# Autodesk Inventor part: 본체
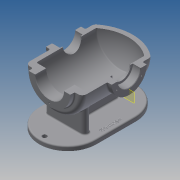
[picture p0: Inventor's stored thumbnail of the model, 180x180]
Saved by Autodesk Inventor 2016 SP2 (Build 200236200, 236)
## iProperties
Created: 2016-02
Part Number: 본체
Material: 알루미늄 6061
Document SubType Name: Modeling
Designer: mduedu
Density: 2.71 g/cm^3
Mass: 2160.77 g
Surface Area: 1521.8 cm^2
Volume: 797.331 cm^3
Appearance: 기본값
Author: mduedu
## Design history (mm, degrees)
sketch "스케치2"
  geometry: L1 (0, 90)-(0, -90); L2 (65, -65.993)-(65, 90); L3 (65, 90)-(0, 90); A1 r 100 centre (0, 10) between (0, -90) and (65, -65.993); 2 further points
  constraints: 6 end point, 2 point on circle, 1 centre point, 1 coincident, 1 horizontal, 1 midpoint, 1 parallel, 1 point on line, 1 vertical
  dimensions: "d3" = 180 distance of L1.start L1.end; "d5" = 130 diameter of L2 L1; "d6" = 100 radius of A1
revolve "회전1" sketch "스케치2" stored, may be unused: angle "d7" = 90 deg
sketch "스케치3"
  geometry: C1 r 47.5 at (0, 0); 1 further point
  constraints: 1 centre point, 1 coincident
  dimensions: "d8" = 95 diameter of C1
extrude "돌출2" join sketch "스케치3" distance "d10" = 10; taper "d11" = 0 deg
sketch "스케치5"
  geometry: L1 (47.5, 100)-(47.5, 90) reference; L2 (47.5, 90)-(65, 90) reference; L3 (65, 90)-(65, -65.993) reference; L4 (-65, -65.993)-(-65, 90) reference; L5 (-65, 90)-(-47.5, 90) reference; L6 (-47.5, 90)-(-47.5, 100) reference; L7 (-47.5, 100)-(47.5, 100) reference; L8 (55, 75)-(55, -61.239); L9 (0, 75)-(55, 75); L10 (0, 75)-(0, -80); A1 r 100 centre (0, 10) between (-65, -65.993) and (0, -90) reference; A2 r 100 centre (0, 10) between (0, -90) and (65, -65.993) reference; A3 r 90 centre (0, 10) between (0, -80) and (55, -61.239); 1 further point
  constraints: 6 end point, 2 point on circle, 1 centre point, 1 parallel, 1 perpendicular, 1 point on line, 1 vertical
  dimensions: "d13" = 10 distance between parallel lines of L3 L8; "d14" = 10 radial gap between concentric circles of A3 A1; "d15" = 15 distance between parallel lines of L9 L2
revolve "회전2" sketch "스케치5" stored, may be unused: angle "d16" = 90 deg
hole "구멍1" diameter "d19" = 65; stored, may be unused: countersink angle "d23" = 90 deg, drill point angle "d25" = 118 deg; dims "d17" = 10, "d18" = 10, "d20" = 6, "d21" = 4, "d22" = 2, "d24" = 8
node "작업 평면1"
sketch "스케치6"
  geometry: L1 (47.5, 100)-(-47.5, 100) reference; C1 r 40 at (0, -7); 1 further point
  constraints: 1 centre point, 1 vertical alignment
  dimensions: "d27" = 80 diameter of C1; "d29" = 107 distance from line of C1.centre L1
extrude "돌출3" join sketch "스케치6" stored distance "d30" = 10; taper "d31" = 0 deg
hole "구멍2" diameter "d34" = 42; stored, may be unused: countersink angle "d38" = 90 deg, drill point angle "d40" = 118 deg; dims "d32" = 10, "d33" = 10, "d35" = 6, "d36" = 52, "d37" = 18, "d39" = 8
sketch "스케치7" dims "d41" = 65
  geometry: C1 r 40 at (0, 0) reference; 3 further points
  constraints: 2 vertical alignment, 1 coincident, 2 other
hole "구멍3" sketch "스케치7" at (0, 32.5) diameter "d43" = 3.242; stored, may be unused: countersink angle "d47" = 90 deg, drill point angle "d49" = 118 deg; dims "d44" = 11, "d45" = 13, "d46" = 18, "d48" = 13
sketch "스케치8" dims "d53" = 80
  geometry: 3 further points
  constraints: 2 vertical alignment, 1 coincident, 2 other
hole "구멍4" sketch "스케치8" at (0, -40) diameter "d56" = 3.242; stored, may be unused: countersink angle "d60" = 90 deg, drill point angle "d62" = 118 deg; dims "d57" = 11, "d58" = 13, "d59" = 18, "d61" = 13
fillet "모깎기1" dims "d66" = 10
fillet "모깎기2" dims "d67" = 3
fillet "모깎기3" dims "d68" = 1
chamfer "모따기1" distance "d69" = 1; stored, may be unused: second distance "d70" = 2, angle "d71" = 45 deg
node "작업 평면5"
sketch "스케치10"
  geometry: L1 (-45, 66)-(45, 66); L2 (45, 66)-(45, 50); L3 (45, 50)-(-45, 50); L4 (-45, 50)-(-45, 66); 2 further points
  constraints: 8 end point, 2 horizontal, 2 vertical, 1 midpoint, 1 vertical alignment
  dimensions: "d177" = 50 distance from line of L3 point (0, 0); "d178" = 90 distance of L1.start L1.end; "d179" = 16 distance of L3.end L1.start
extrude "돌출5" join sketch "스케치10" stored distance "d84" = 10; taper "d85" = 0 deg
sketch "스케치21" dims "d180" = 220, "d182" = 130
  geometry: L1 (65, 58)-(-65, 58); L2 (-65, 58)-(-65, -32); L3 (-65, -32)-(65, -32); L4 (65, -32)-(65, 58); L5 (45, 50)-(45, 66) reference; 4 further points
  constraints: 8 end point, 3 horizontal alignment, 3 midpoint, 2 parallel, 1 horizontal, 1 perpendicular, 1 vertical alignment, 4 other
extrude "돌출13" join sketch "스케치21" distance "d183" = 10; taper "d184" = 0 deg
sketch "스케치11"
  geometry: L1 (-65, 80)-(-65, -61.239) reference; L2 (-100, -97)-(-100, -32) reference; L3 (-65, -45.829)-(-100, -52); L4 (-100, -97)-(-110, -97) reference; 1 further point
  constraints: 2 end point, 2 point on line
  dimensions: "d185" = 45 distance from line of L3.end L4; "d186" = 100 deg angle of L2 L3
feature "리브1" sketch "스케치11" dims "d88" = 1, "d89" = 16, "d90" = 0, "d91" = 0, "d92" = 1, "d93" = 1
fillet "모깎기12"
fillet "모깎기13"
fillet "모깎기16" dims "d167" = 3
fillet "모깎기18"
fillet "모깎기17" dims "d168" = 3
fillet "모깎기19" dims "d187" = 3
node "작업 평면6"
sketch "스케치19"
  geometry: L1 (75, -47)-(75, 33) reference; L2 (-75, -47)-(-75, 33) reference; L3 (75, -7)-(-75, -7); C1 r 22.5 at (0, -7); 1 further point
  constraints: 3 midpoint, 2 end point, 1 centre point
  dimensions: "d149" = 45 diameter of C1
extrude "돌출11" join sketch "스케치19" stored distance "d150" = 10; taper "d151" = 0 deg
hole "구멍6" diameter "d154" = 33.376; stored, may be unused: countersink angle "d158" = 90 deg, drill point angle "d160" = 118 deg; dims "d155" = 6, "d156" = 4, "d157" = 2, "d159" = 8, "d190" = 10, "d191" = 10
fillet "모깎기11" dims "d161" = 3
chamfer "모따기3" distance "d164" = 1; stored, may be unused: second distance "d165" = 2, angle "d166" = 45 deg
node "작업 평면9"
  node "작업 평면8"
sketch "스케치22"
  geometry: L1 (-65, -58)-(-65, 32) reference; L2 (65, 32)-(65, -58) reference; L3 (53, 32)-(53, -58); L4 (-53, -58)-(-53, 32); C1 r 5 at (0, -111); A1 r 65 centre (0, -58) between (-65, -58) and (65, -58) reference; A2 r 65 centre (0, 32) between (65, 32) and (-65, 32) reference; A3 r 53 centre (0, 32) between (53, 32) and (-53, 32); A4 r 53 centre (0, -58) between (-53, -58) and (53, -58); 1 further point
  constraints: 5 point on circle, 4 end point, 3 centre point, 3 other
  dimensions: "d201" = 12 distance between parallel lines of L3 L2; "d202" = 10 diameter of C1
extrude "돌출14" cut sketch "스케치22" stored distance "d194" = 10; taper "d195" = 0 deg
fillet "모깎기21" dims "d196" = 3
feature "분할1"
sketch "스케치23"
  geometry: L1 (-65, 32)-(-65, -58) reference; L2 (65, -58)-(65, 32) reference; L3 (-65, -13)-(65, -13); 2 further points
  constraints: 2 end point, 2 midpoint, 1 point on line, 1 other
  dimensions: "d197" = 12 distance from line of point (53, -13) L2
feature "엠보싱2" sketch "스케치23" dims "d3" = 180, "d5" = 130, "d6" = 100, "d198" = 0.5, "d199" = 0
node "작업 평면10"
node "솔리드2"
pattern_circular "원형 패턴1" dims angle "d51" = 360 deg
mirror "대칭1"
pattern_circular "원형 패턴2" dims angle "d64" = 360 deg
mirror "대칭3"
node "절단 모서리 투영1"
other parameters: "d26" = 75, "d136" = 175
